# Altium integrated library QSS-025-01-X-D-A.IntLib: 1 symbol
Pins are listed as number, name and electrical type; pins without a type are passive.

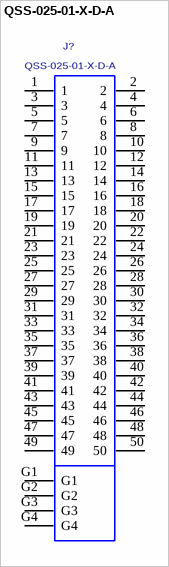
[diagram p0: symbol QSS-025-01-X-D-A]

## QSS-025-01-X-D-A
designator J?
HS Socket Assembly, 0.635mm, Double Row.; MANUFACTURER: SAMTEC
footprint QSS-025-01-X-D-A
pins: 1, 2, 3, 4, 5, 6, 7, 8, 9, 10, 11, 12, 13, 14, 15, 16, 17, 18, 19, 20, 21, 22, 23, 24, 25, 26, 27, 28, 29, 30, 31, 32, 33, 34, 35, 36, 37, 38, 39, 40, 41, 42, 43, 44, 45, 46, 47, 48, 49, 50, G1, G2, G3, G4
